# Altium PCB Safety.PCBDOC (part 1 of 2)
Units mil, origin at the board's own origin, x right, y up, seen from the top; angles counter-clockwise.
Board outline 11000 x 4400 mil, 6 copper layers (Top Layer, Multi Plane 1, Signal Layer1, Signal Layer2, Multi Plane 2, Bottom Layer); 613 components, 553 nets, 1937 pads, 0 vias.
Unrouted connection lines stored in the file: 1304.
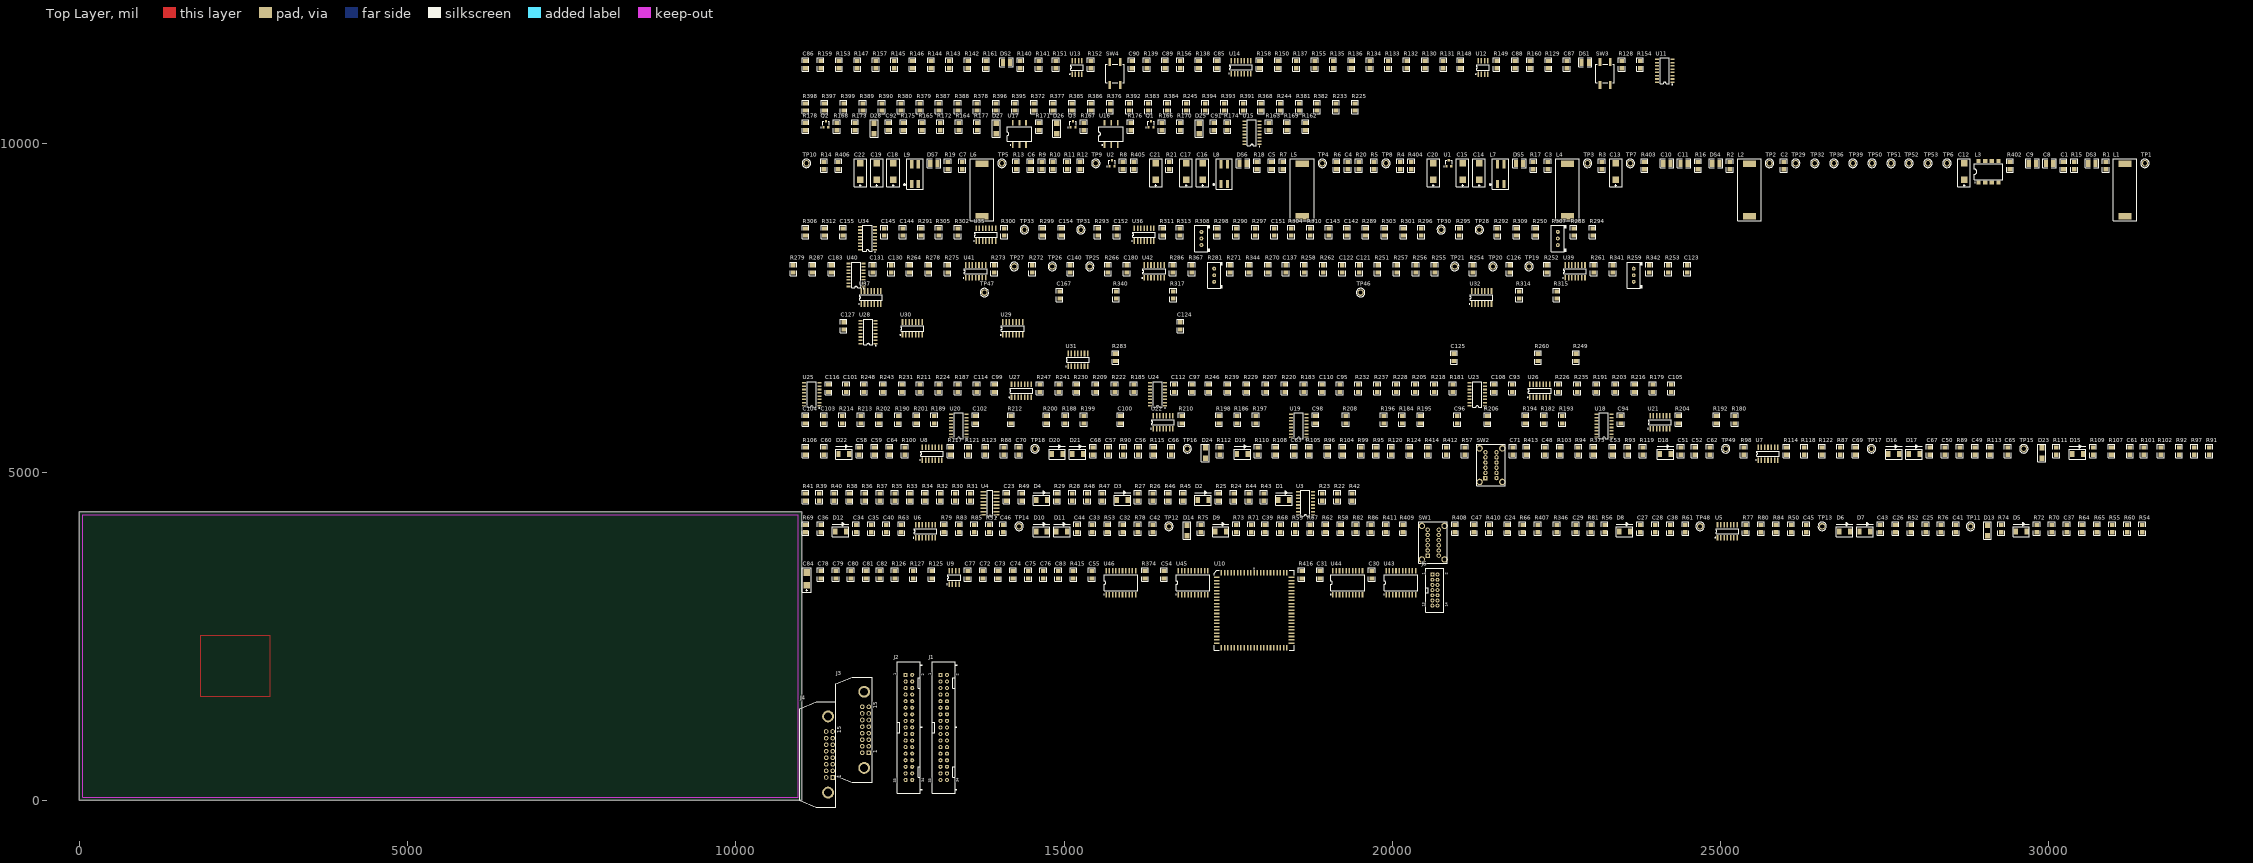
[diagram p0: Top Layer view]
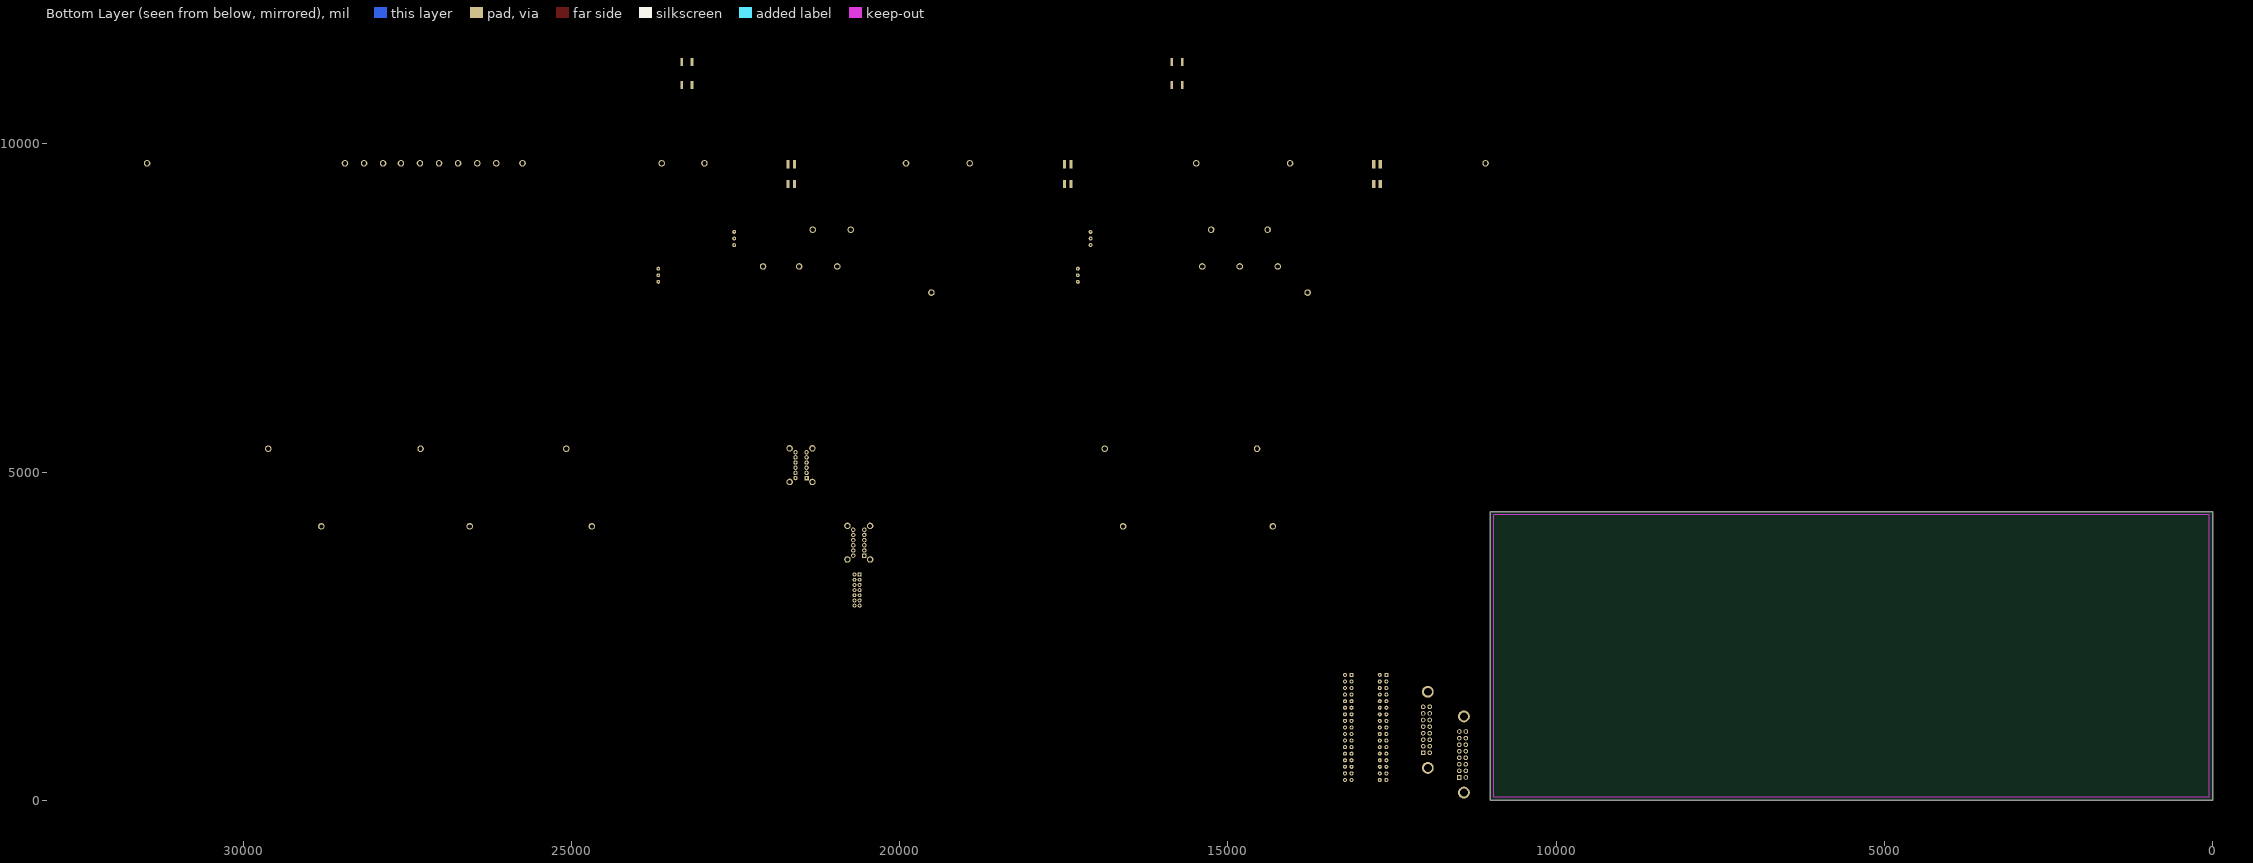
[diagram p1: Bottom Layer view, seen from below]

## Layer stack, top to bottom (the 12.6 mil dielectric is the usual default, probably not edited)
Top Layer: signal copper 1.4
Dielectric: core 12.6, FR-4, Dk 4.8
Multi Plane 1: signal copper 1.4
Dielectric: prepreg 12.6, FR-4, Dk 4.8
Signal Layer1: signal copper 1.4
Dielectric: core 12.6, FR-4, Dk 4.8
Signal Layer2: signal copper 1.4
Dielectric: prepreg 12.6, FR-4, Dk 4.8
Multi Plane 2: signal copper 1.4
Dielectric: core 12.6, FR-4, Dk 4.8
Bottom Layer: signal copper 1.4

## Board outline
0,0 11000,0 11000,4400 0,4400

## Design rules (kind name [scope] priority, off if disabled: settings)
RoomDefinition Sheet_Symbol_Overspeed [InComponentClass('Sheet_Symbol_Overspeed')] p1: confinementstyle=ConfineIn formatcopy=TRUE outline -1500,-2150 500,-2150 500,-1150 -1500,-1150
RoomDefinition Sheet_Symbol_Overcurrent_3 [InComponentClass('Sheet_Symbol_Overcurrent')] p2: confinementstyle=ConfineIn formatcopy=TRUE outline -1500,-2150 500,-2150 500,-1150 -1500,-1150
RoomDefinition Sheet_Symbol_Overcurrent_2 [InComponentClass('Sheet_Symbol_Overcurrent')] p3: confinementstyle=ConfineIn formatcopy=TRUE outline -1500,-2150 500,-2150 500,-1150 -1500,-1150
RoomDefinition Sheet_Symbol_Overcurrent_1 [InComponentClass('Sheet_Symbol_Overcurrent')] p4: confinementstyle=ConfineIn formatcopy=TRUE outline -1500,-2150 500,-2150 500,-1150 -1500,-1150
RoomDefinition Sheet_Symbol_Overcurrent [InComponentClass('Sheet_Symbol_Overcurrent')] p5: confinementstyle=ConfineIn formatcopy=TRUE outline -1500,-2150 500,-2150 500,-1150 -1500,-1150
RoomDefinition Sheet_Symbol_Input_Buffer_1 [InComponentClass('Sheet_Symbol_Input_Buffer')] p6: confinementstyle=ConfineIn formatcopy=TRUE outline -1500,-2150 500,-2150 500,-1150 -1500,-1150
RoomDefinition SB_PG1 [InComponentClass('SB_PG1')] p7: confinementstyle=ConfineIn formatcopy=TRUE outline -1500,-2150 500,-2150 500,-1150 -1500,-1150
RoomDefinition Sheet_Symbol_CPLD [InComponentClass('Sheet_Symbol_CPLD')] p8: confinementstyle=ConfineIn formatcopy=TRUE outline 11000,2273 20860,2273 20860,3650 11000,3650
RoomDefinition Sheet_Symbol_Dec_Tach [InComponentClass('Sheet_Symbol_Dec_Tach')] p9: confinementstyle=ConfineIn formatcopy=TRUE outline 11000,3601 31552,3601 31552,4351 11000,4351
RoomDefinition Sheet_Symbol_Encoder [InComponentClass('Sheet_Symbol_Encoder')] p10: confinementstyle=ConfineIn formatcopy=TRUE outline 11000,4301 19520,4301 19520,4831 11000,4831
RoomDefinition Sheet_Symbol_HA_Tach [InComponentClass('Sheet_Symbol_HA_Tach')] p11: confinementstyle=ConfineIn formatcopy=TRUE outline 11000,4782 32552,4782 32552,5532 11000,5532
RoomDefinition Sheet_Symbol_Input_Buffer [InComponentClass('Sheet_Symbol_Input_Buffer')] p12: confinementstyle=ConfineIn formatcopy=TRUE outline 11000,5961 24416,5961 24416,6490 11000,6490
RoomDefinition Sheet_Symbol_Power_Filter [InComponentClass('Sheet_Symbol_Power_Filter')] p13: confinementstyle=ConfineIn formatcopy=TRUE outline 11000,8820 31557,8820 31557,9880 11000,9880
RoomDefinition Sheet_Symbol_Relays [InComponentClass('Sheet_Symbol_Relays')] p14: confinementstyle=ConfineIn formatcopy=TRUE outline 11000,9930 18855,9930 18855,10474 11000,10474
RoomDefinition Sheet_Symbol_Spares [InComponentClass('Sheet_Symbol_Spares')] p15: confinementstyle=ConfineIn formatcopy=TRUE outline 11000,10450 19619,10450 19619,10774 11000,10774
RoomDefinition Sheet_Symbol_WD [InComponentClass('Sheet_Symbol_WD')] p16: confinementstyle=ConfineIn formatcopy=TRUE outline 11000,10823 24302,10823 24302,11419 11000,11419

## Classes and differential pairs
component class SB_PG1: J1 J2 J3 J4 J5
component class Sheet_Symbol_CPLD: C30 C31 C54 C55 C72 C73 C74 C75 C76 C77 C78 C79 C80 C81 C82 C83 C84 J6 R125 R126 R127 R374 R415 R416 U9 U10 U43 U44 U45 U46
component class Sheet_Symbol_Dec_Tach: C24 C25 C26 C27 C28 C29 C32 C33 C34 C35 C36 C37 C38 C39 C40 C41 C42 C43 C44 C45 C46 C47 D5 D6 D7 D8 D9 D10 D11 D12 D13 D14 R50 R51 R52 R53 R54 R55 R56 R58 R59 R60 R61 R62 R63 R64 R65 R66 R67 R68 R69 R70 R71 R72 R73 R74 R75 R76 R77 R78 R79 R80 R81 R82 R83 R84 R85 R86 R346 R407 R408 R409 R410 R411 SW1 TP11 TP12 TP13 TP14 TP48 U5 U6
component class Sheet_Symbol_Encoder: C23 D1 D2 D3 D4 R22 R23 R24 R25 R26 R27 R28 R29 R30 R31 R32 R33 R34 R35 R36 R37 R38 R39 R40 R41 R42 R43 R44 R45 R46 R47 R48 R49 U3 U4
component class Sheet_Symbol_HA_Tach: C48 C49 C50 C51 C52 C53 C56 C57 C58 C59 C60 C61 C62 C63 C64 C65 C66 C67 C68 C69 C70 C71 D15 D16 D17 D18 D19 D20 D21 D22 D23 D24 R57 R87 R88 R89 R90 R91 R92 R93 R94 R95 R96 R97 R98 R99 R100 R101 R102 R103 R104 R105 R106 R107 R108 R109 R110 R111 R112 R113 R114 R115 R117 R118 R119 R120 R121 R122 R123 R124 R373 R412 R413 R414 SW2 TP15 TP16 TP17 TP18 TP49 U7 U8
component class Sheet_Symbol_Input_Buffer: C93 C95 C97 C99 C101 C105 C108 C110 C112 C114 C116 R179 R181 R183 R185 R187 R191 R203 R205 R207 R209 R211 R216 R218 R220 R222 R224 R226 R228 R229 R230 R231 R232 R235 R237 R239 R241 R243 R246 R247 R248 U23 U24 U25 U26 U27
component class Sheet_Symbol_Overcurrent: C121 C122 C123 C126 C130 C131 C137 C140 C180 C183 R251 R252 R253 R254 R255 R256 R257 R258 R259 R261 R262 R264 R266 R270 R271 R272 R273 R275 R278 R279 R281 R286 R287 R341 R342 R344 R367 R369 TP19 TP20 TP21 TP25 TP26 TP27 U39 U40 U41 U42
component class Sheet_Symbol_Overspeed: C142 C143 C144 C145 C151 C152 C154 C155 R250 R288 R289 R290 R291 R292 R293 R294 R295 R296 R297 R298 R299 R300 R301 R302 R303 R304 R305 R306 R307 R308 R309 R310 R311 R312 R313 R370 TP28 TP30 TP31 TP33 U34 U35 U36
component class Sheet_Symbol_Power_Filter: C1 C2 C3 C4 C5 C6 C7 C8 C9 C10 C11 C12 C13 C14 C15 C16 C17 C18 C19 C20 C21 C22 DS3 DS4 DS5 DS6 DS7 L1 L2 L3 L4 L5 L6 L7 L8 L9 R1 R2 R3 R4 R5 R6 R7 R8 R9 R10 R11 R12 R13 R14 R15 R16 R17 R18 R19 R20 R21 R402 R403 R404 R405 R406 TP1 TP2 TP3 TP4 TP5 TP6 TP7 TP8 TP9 TP10 TP29 TP32 TP36 TP39 TP50 TP51 TP52 TP53 U1 U2
component class Sheet_Symbol_Relays: C91 C92 D25 D26 D27 D28 Q1 Q2 Q3 R162 R163 R164 R165 R166 R167 R168 R169 R170 R171 R172 R173 R174 R175 R176 R177 R178 U15 U16 U17
component class Sheet_Symbol_Spares: R225 R233 R244 R245 R368 R372 R376 R377 R378 R379 R380 R381 R382 R383 R384 R385 R386 R387 R388 R389 R390 R391 R392 R393 R394 R395 R396 R397 R398 R399
component class Sheet_Symbol_WD: C85 C86 C87 C88 C89 C90 DS1 DS2 R128 R129 R130 R131 R132 R133 R134 R135 R136 R137 R138 R139 R140 R141 R142 R143 R144 R145 R146 R147 R148 R149 R150 R151 R152 R153 R154 R155 R156 R157 R158 R159 R160 R161 SW3 SW4 U11 U12 U13 U14

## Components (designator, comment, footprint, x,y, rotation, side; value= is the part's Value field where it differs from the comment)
C1 "1uF" 1206 30222,9668 r90 top
C2 "1uF" 1206 25959,9668 r90 top
C3 "1uF" 1206 22367,9668 r90 top
C4 "1uF" 1206 19318,9668 r90 top
C5 "1uF" 1206 18157,9668 r90 top
C6 "1uF" 1206 14488,9668 r90 top
C7 "1uF" 1206 13447,9668 r90 top
C8 "22uF_15V" 1210 30010,9702 r0 top
C9 "22uF_15V" 1210 29747,9702 r0 top
C10 "22uF_15V" 1210 24180,9702 r0 top
C11 "22uF_15V" 1210 24443,9702 r0 top
C12 "100uF_25V" CAP_EIA_7343 28707,9578 r90 top
C13 "100uF_25V" CAP_EIA_7343 23403,9578 r90 top
C14 "100uF_25V" CAP_EIA_7343 21319,9578 r90 top
C15 "100uF_25V" CAP_EIA_7343 21068,9578 r90 top
C16 "100uF_25V" CAP_EIA_7343 17108,9578 r90 top
C17 "100uF_25V" CAP_EIA_7343 16857,9578 r90 top
C18 "100uF_25V" CAP_EIA_7343 12398,9578 r90 top
C19 "100uF_25V" CAP_EIA_7343 12147,9578 r90 top
C20 "470uF_10V" CAP_EIA_7343 20623,9578 r90 top
C21 "470uF_10V" CAP_EIA_7343 16397,9578 r90 top
C22 "470uF_10V" CAP_EIA_7343 11896,9578 r90 top
C23 "0.1uF" 1206 14122,4619 r90 top
C24 "1uF" 1206 21753,4139 r90 top
C25 "0.1uF" 1206 28122,4139 r90 top
C26 "0.1uF" 1206 27662,4139 r90 top
C27 "0.1uF" 1206 23772,4139 r90 top
C28 "0.1uF" 1206 24002,4139 r90 top
C29 "0.1uF" 1206 22792,4139 r90 top
C30 "0.1uF" 1206 19686,3438 r90 top
C31 "0.1uF" 1206 18896,3438 r90 top
C32 "0.1uF" 1206 15890,4139 r90 top
C33 "0.1uF" 1206 15430,4139 r90 top
C34 "0.1uF" 1206 11831,4139 r90 top
C35 "0.1uF" 1206 12061,4139 r90 top
C36 "0.1uF" 1206 11291,4139 r90 top
C37 "0.022uF" 1206 30272,4139 r90 top
C38 "0.022uF" 1206 24232,4139 r90 top
C39 "0.022uF" 1206 18060,4139 r90 top
C40 "0.022uF" 1206 12291,4139 r90 top
C41 "2200pF" 1206 28582,4139 r90 top
C42 "2200pF" 1206 16350,4139 r90 top
C43 "0.068uF" 1206 27432,4139 r90 top
C44 "0.068uF" 1206 15201,4139 r90 top
C45 "0.33uF" 1206 26302,4139 r90 top
C46 "0.33uF" 1206 14070,4139 r90 top
C47 "0.22uF" 1206 21243,4139 r90 top
C48 "1uF" 1206 22322,5320 r90 top
C49 "0.1uF" 1206 28872,5320 r90 top
C50 "0.1uF" 1206 28412,5320 r90 top
C51 "0.1uF" 1206 24392,5320 r90 top
C52 "0.1uF" 1206 24602,5320 r90 top
C53 "0.1uF" 1206 23352,5320 r90 top
C54 "0.1uF" 1206 16521,3438 r90 top
C55 "0.1uF" 1206 15421,3438 r90 top
C56 "0.1uF" 1206 16130,5320 r90 top
C57 "0.1uF" 1206 15670,5320 r90 top
C58 "0.1uF" 1206 11881,5320 r90 top
C59 "0.1uF" 1206 12111,5320 r90 top
C60 "0.1uF" 1206 11341,5320 r90 top
C61 "0.022uF" 1206 31232,5320 r90 top
C62 "0.022uF" 1206 24832,5320 r90 top
C63 "0.022uF" 1206 18500,5320 r90 top
C64 "0.022uF" 1206 12341,5320 r90 top
C65 "2200pF" 1206 29372,5320 r90 top
C66 "2200pF" 1206 16630,5320 r90 top
C67 "0.068uF" 1206 28182,5320 r90 top
C68 "0.068uF" 1206 15440,5320 r90 top
C69 "0.33uF" 1206 27052,5320 r90 top
C70 "0.33uF" 1206 14310,5320 r90 top
C71 "0.22uF" 1206 21833,5320 r90 top
C72 "1uF" 1206 13762,3438 r90 top
C73 "1uF" 1206 13992,3438 r90 top
C74 "1uF" 1206 14222,3438 r90 top
C75 "1uF" 1206 14452,3438 r90 top
C76 "1uF" 1206 14682,3438 r90 top
C77 "0.1uF" 1206 13532,3438 r90 top
C78 "0.1uF" 1206 11291,3438 r90 top
C79 "0.1uF" 1206 11521,3438 r90 top
C80 "0.1uF" 1206 11751,3438 r90 top
C81 "0.1uF" 1206 11981,3438 r90 top
C82 "0.1uF" 1206 12191,3438 r90 top
C83 "0.01uF" 1206 14911,3438 r90 top
C84 "10uF_25V" CAP_EIA_6032 11079,3375 r90 top
C85 "1uF" 1206 17327,11207 r90 top
C86 "1uF" 1206 11061,11207 r90 top
C87 "0.1uF" 1206 22656,11207 r90 top
C88 "0.1uF" 1206 21866,11207 r90 top
C89 "0.1uF" 1206 16537,11207 r90 top
C90 "0.1uF" 1206 16027,11207 r90 top
C91 "1uF" 1206 17276,10262 r90 top
C92 "1uF" 1206 12325,10262 r90 top
C93 "1uF" 1206 21826,6278 r90 top
C94 "1uF" 1206 23476,5799 r90 top
C95 "1uF" 1206 19198,6278 r90 top
C96 "1uF" 1206 20987,5799 r90 top
C97 "1uF" 1206 16948,6278 r90 top
C98 "1uF" 1206 18828,5799 r90 top
C99 "1uF" 1206 13940,6278 r90 top
C100 "1uF" 1206 15859,5799 r90 top
C101 "1uF" 1206 11680,6278 r90 top
C102 "1uF" 1206 13650,5799 r90 top
C103 "1uF" 1206 11341,5799 r90 top
C104 "1uF" 1206 11061,5799 r90 top
C105 "0.1uF" 1206 24246,6278 r90 top
C108 "1uF" 1206 21547,6278 r90 top
C110 "1uF" 1206 18928,6278 r90 top
C112 "1uF" 1206 16678,6278 r90 top
C114 "1uF" 1206 13670,6278 r90 top
C116 "1uF" 1206 11410,6278 r90 top
C121 "1uF" 1206 19494,8097 r90 top
C122 "1uF" 1206 19234,8097 r90 top
C123 "0.1uF" 1206 24490,8097 r90 top
C124 "0.1uF" 1206 16770,7228 r90 top
C125 "0.1uF" 1206 20937,6749 r90 top
C126 "0.1uF" 1206 21785,8097 r90 top
C127 "0.1uF" 1206 11641,7228 r90 top
C130 "1uF" 1206 12365,8097 r90 top
C131 "1uF" 1206 12085,8097 r90 top
C137 "0.1uF" 1206 18375,8097 r90 top
C140 "0.1uF" 1206 15095,8097 r90 top
C142 "1uF" 1206 19309,8657 r90 top
C143 "1uF" 1206 19029,8657 r90 top
C144 "1uF" 1206 12540,8657 r90 top
C145 "1uF" 1206 12260,8657 r90 top
C151 "0.1uF" 1206 18199,8657 r90 top
C152 "0.1uF" 1206 15800,8657 r90 top
C154 "0.1uF" 1206 14960,8657 r90 top
C155 "0.1uF" 1206 11631,8657 r90 top
C167 "0.1uF" 1206 14931,7699 r90 top
C180 "0.1uF" 1206 15955,8097 r90 top
C183 "0.1uF" 1206 11456,8097 r90 top
D1 "RS1DB-13" "DO-214AA (SMB) & MARKING" 18346,4575 r0 top
D2 "RS1DB-13" "DO-214AA (SMB) & MARKING" 17116,4575 r0 top
D3 "RS1DB-13" "DO-214AA (SMB) & MARKING" 15886,4575 r0 top
D4 "RS1DB-13" "DO-214AA (SMB) & MARKING" 14656,4575 r0 top
D5 "RS1DB-13" "DO-214AA (SMB) & MARKING" 29577,4095 r0 top
D6 "RS1DB-13" "DO-214AA (SMB) & MARKING" 26887,4095 r0 top
D7 "RS1DB-13" "DO-214AA (SMB) & MARKING" 27197,4095 r0 top
D8 "RS1DB-13" "DO-214AA (SMB) & MARKING" 23537,4095 r0 top
D9 "RS1DB-13" "DO-214AA (SMB) & MARKING" 17385,4095 r0 top
D10 "RS1DB-13" "DO-214AA (SMB) & MARKING" 14655,4095 r0 top
D11 "RS1DB-13" "DO-214AA (SMB) & MARKING" 14965,4095 r0 top
D12 "RS1DB-13" "DO-214AA (SMB) & MARKING" 11595,4095 r0 top
D13 "1SMA10CAT3G" "DO-214AC (SMA)" 29063,4111 r90 top
D14 "1SMA10CAT3G" "DO-214AC (SMA)" 16871,4111 r90 top
D15 "RS1DB-13" "DO-214AA (SMB) & MARKING" 30437,5276 r0 top
D16 "RS1DB-13" "DO-214AA (SMB) & MARKING" 27637,5276 r0 top
D17 "RS1DB-13" "DO-214AA (SMB) & MARKING" 27947,5276 r0 top
D18 "RS1DB-13" "DO-214AA (SMB) & MARKING" 24157,5276 r0 top
D19 "RS1DB-13" "DO-214AA (SMB) & MARKING" 17715,5276 r0 top
D20 "RS1DB-13" "DO-214AA (SMB) & MARKING" 14895,5276 r0 top
D21 "RS1DB-13" "DO-214AA (SMB) & MARKING" 15205,5276 r0 top
D22 "RS1DB-13" "DO-214AA (SMB) & MARKING" 11645,5276 r0 top
D23 "1SMA10CAT3G" "DO-214AC (SMA)" 29892,5292 r90 top
D24 "1SMA10CAT3G" "DO-214AC (SMA)" 17151,5292 r90 top
D25 "SMAJ26CA" "DO-214AC (SMA)" 17056,10234 r90 top
D26 "SMAJ26CA" "DO-214AC (SMA)" 14886,10234 r90 top
D27 "SMAJ26CA" "DO-214AC (SMA)" 13964,10234 r90 top
D28 "SMAJ26CA" "DO-214AC (SMA)" 12105,10234 r90 top
DS1 "LTST-C930KGKT" 1210 22937,11241 r0 top
DS2 "LTST-C930KGKT" 1210 14121,11241 r0 top
DS3 "LTST-C930KGKT" 1210 30654,9702 r0 top
DS4 "LTST-C930KGKT" 1210 24926,9702 r0 top
DS5 "LTST-C930KGKT" 1210 21935,9702 r0 top
DS6 "LTST-C930KGKT" 1210 17725,9702 r0 top
DS7 "LTST-C930KGKT" 1210 13015,9702 r0 top
J1 "Header_50_(25X2)_STR_SHD_LATCH_col1" HEADER_17x2_SHROUDED 13116,1912 r0 top
J2 "Header_50_(25X2)_STR_SHD_LATCH_col1" HEADER_17x2_SHROUDED 12586,1912 r0 top
J3 "Header_14_(7X2)_STR_SHD_LATCH_col1" 5499141-3 12025,825 r90 top
J4 "Header_16_(8X2)_STR_SHD_LATCH_col1" 5499141-3 11475,450 r90 top
J6 "Header_14_(7X2)_STR_SHD_col2" HDR_87831-1420 20608,3440 r0 top
L1 "8532-46LTR" 8532_inductor 31156,9300 r90 top
L2 "8532-46LTR" 8532_inductor 25438,9300 r90 top
L3 "ZJYS51R5-M4PAT-01" ZJYS51R5-M4PA_INDCUTOR 29079,9576 r0 top
L4 "8532-38LTR" 8532_inductor 22667,9300 r90 top
L5 "8532-38LTR" 8532_inductor 18627,9300 r90 top
L6 "8532-38LTR" 8532_inductor 13747,9300 r90 top
L7 "50105C" 5000_inductor 21649,9540 r90 top
L8 "50105C" 5000_inductor 17439,9540 r90 top
L9 "50105C" 5000_inductor 12728,9540 r90 top
Q1 "MMBT3906" SOT23 16322,10298 r0 top
Q2 "MMBT3906" SOT23 11371,10298 r0 top
Q3 "MMBT3904" SOT23 15136,10298 r0 top
R1 "0_jumper" 1206 30865,9668 r90 top
R2 "0_jumper" 1206 25138,9668 r90 top
R3 "0_jumper" 1206 23188,9668 r90 top
R4 "0_jumper" 1206 20118,9668 r90 top
R5 "0_jumper" 1206 19718,9668 r90 top
R6 "0_jumper" 1206 19148,9668 r90 top
R7 "0_jumper" 1206 18327,9668 r90 top
R8 "0_jumper" 1206 15892,9668 r90 top
R9 "0_jumper" 1206 14658,9668 r90 top
R10 "0_jumper" 1206 14828,9668 r90 top
R11 "0_jumper" 1206 15047,9668 r90 top
R12 "0_jumper" 1206 15247,9668 r90 top
R13 "0_jumper" 1206 14268,9668 r90 top
R14 "0_jumper" 1206 11341,9668 r90 top
R15 "15.8" 1206 30383,9668 r90 top
R16 "15.8" 1206 24655,9668 r90 top
R17 "3.01" 1206 22147,9668 r90 top
R18 "3.01" 1206 17937,9668 r90 top
R19 "3.01" 1206 13227,9668 r90 top
R20 "4870" 1206 19488,9668 r90 top
R21 "4870" 1206 16602,9668 r90 top
R22 "0_jumper" 1206 19160,4619 r90 top
R23 "0_jumper" 1206 18930,4619 r90 top
R24 "0_jumper" 1206 17581,4619 r90 top
R25 "0_jumper" 1206 17351,4619 r90 top
R26 "0_jumper" 1206 16351,4619 r90 top
R27 "0_jumper" 1206 16122,4619 r90 top
R28 "0_jumper" 1206 15122,4619 r90 top
R29 "0_jumper" 1206 14892,4619 r90 top
R30 "0_jumper" 1206 13340,4619 r90 top
R31 "0_jumper" 1206 13570,4619 r90 top
R32 "0_jumper" 1206 13111,4619 r90 top
R33 "0_jumper" 1206 12651,4619 r90 top
R34 "0_jumper" 1206 12881,4619 r90 top
R35 "0_jumper" 1206 12421,4619 r90 top
R36 "0_jumper" 1206 11961,4619 r90 top
R37 "0_jumper" 1206 12191,4619 r90 top
R38 "0_jumper" 1206 11731,4619 r90 top
R39 "0_jumper" 1206 11271,4619 r90 top
R40 "0_jumper" 1206 11501,4619 r90 top
R41 "0_jumper" 1206 11061,4619 r90 top
R42 "205" 1206 19390,4619 r90 top
R43 "205" 1206 18041,4619 r90 top
R44 "205" 1206 17811,4619 r90 top
R45 "205" 1206 16811,4619 r90 top
R46 "205" 1206 16581,4619 r90 top
R47 "205" 1206 15582,4619 r90 top
R48 "205" 1206 15352,4619 r90 top
R49 "205" 1206 14352,4619 r90 top
R50 "0_jumper" 1206 26072,4139 r90 top
R51 "0_jumper" 1206 13860,4139 r90 top
R52 "4870" 1206 27892,4139 r90 top
R53 "4870" 1206 15660,4139 r90 top
R54 "200000" 1206 31422,4139 r90 top
R55 "200000" 1206 30962,4139 r90 top
R56 "200000" 1206 23232,4139 r90 top
R57 "200000" 1206 21100,5320 r90 top
R58 "200000" 1206 19210,4139 r90 top
R59 "200000" 1206 18520,4139 r90 top
R60 "10000" 1206 31192,4139 r90 top
R61 "10000" 1206 24462,4139 r90 top
R62 "10000" 1206 18980,4139 r90 top
R63 "10000" 1206 12521,4139 r90 top
R64 "301000" 1206 30502,4139 r90 top
R65 "301000" 1206 30732,4139 r90 top
R66 "301000" 1206 21983,4139 r90 top
R67 "301000" 1206 18750,4139 r90 top
R68 "301000" 1206 18290,4139 r90 top
R69 "301000" 1206 11061,4139 r90 top
R70 "2000" 1206 30042,4139 r90 top
R71 "2000" 1206 17851,4139 r90 top
R72 "6810" 1206 29812,4139 r90 top
R73 "6810" 1206 17621,4139 r90 top
R74 "100" 1206 29272,4139 r90 top
R75 "100" 1206 17081,4139 r90 top
R76 "47500" 1206 28352,4139 r90 top
R77 "47500" 1206 25382,4139 r90 top
R78 "47500" 1206 16120,4139 r90 top
R79 "47500" 1206 13170,4139 r90 top
R80 "68100" 1206 25612,4139 r90 top
R81 "68100" 1206 23022,4139 r90 top
R82 "68100" 1206 19440,4139 r90 top
R83 "68100" 1206 13400,4139 r90 top
R84 "56200" 1206 25842,4139 r90 top
R85 "56200" 1206 13630,4139 r90 top
R86 "33200" 1206 19670,4139 r90 top
R87 "0_jumper" 1206 26822,5320 r90 top
R88 "0_jumper" 1206 14080,5320 r90 top
R89 "4870" 1206 28642,5320 r90 top
R90 "4870" 1206 15900,5320 r90 top
R91 "200000" 1206 32442,5320 r90 top
R92 "200000" 1206 31982,5320 r90 top
R93 "200000" 1206 23582,5320 r90 top
R94 "200000" 1206 22832,5320 r90 top
R95 "200000" 1206 19750,5320 r90 top
R96 "200000" 1206 19010,5320 r90 top
R97 "10000" 1206 32212,5320 r90 top
R98 "10000" 1206 25352,5320 r90 top
R99 "10000" 1206 19520,5320 r90 top
R100 "10000" 1206 12571,5320 r90 top
R101 "301000" 1206 31442,5320 r90 top
R102 "301000" 1206 31702,5320 r90 top
R103 "301000" 1206 22552,5320 r90 top
R104 "301000" 1206 19240,5320 r90 top
R105 "301000" 1206 18730,5320 r90 top
R106 "301000" 1206 11061,5320 r90 top
R107 "2000" 1206 30952,5320 r90 top
R108 "2000" 1206 18220,5320 r90 top
R109 "6810" 1206 30672,5320 r90 top
R110 "6810" 1206 17950,5320 r90 top
R111 "100" 1206 30112,5320 r90 top
R112 "100" 1206 17371,5320 r90 top
R113 "47500" 1206 29102,5320 r90 top
R114 "47500" 1206 26002,5320 r90 top
R115 "47500" 1206 16360,5320 r90 top
R117 "47500" 1206 13270,5320 r90 top
R118 "68100" 1206 26272,5320 r90 top
R119 "68100" 1206 23812,5320 r90 top
R120 "68100" 1206 19980,5320 r90 top
R121 "68100" 1206 13540,5320 r90 top
R122 "56200" 1206 26542,5320 r90 top
R123 "56200" 1206 13800,5320 r90 top
R124 "33200" 1206 20260,5320 r90 top
R125 "4750" 1206 12981,3438 r90 top
R126 "4750" 1206 12421,3438 r90 top
R127 "100000" 1206 12701,3438 r90 top
R128 "0_jumper" 1206 23492,11207 r90 top
R129 "0_jumper" 1206 22376,11207 r90 top
R130 "0_jumper" 1206 20496,11207 r90 top
R131 "0_jumper" 1206 20776,11207 r90 top
R132 "0_jumper" 1206 20216,11207 r90 top
R133 "0_jumper" 1206 19936,11207 r90 top
R134 "0_jumper" 1206 19656,11207 r90 top
R135 "0_jumper" 1206 19096,11207 r90 top
R136 "0_jumper" 1206 19376,11207 r90 top
R137 "0_jumper" 1206 18536,11207 r90 top
R138 "0_jumper" 1206 17047,11207 r90 top
R139 "0_jumper" 1206 16257,11207 r90 top
R140 "0_jumper" 1206 14333,11207 r90 top
R141 "0_jumper" 1206 14613,11207 r90 top
R142 "0_jumper" 1206 13530,11207 r90 top
R143 "0_jumper" 1206 13250,11207 r90 top
R144 "0_jumper" 1206 12971,11207 r90 top
R145 "0_jumper" 1206 12411,11207 r90 top
R146 "0_jumper" 1206 12691,11207 r90 top
R147 "0_jumper" 1206 11851,11207 r90 top
R148 "10000" 1206 21036,11207 r90 top
R149 "10000" 1206 21587,11207 r90 top
R150 "10000" 1206 18256,11207 r90 top
R151 "10000" 1206 14873,11207 r90 top
R152 "10000" 1206 15404,11207 r90 top
R153 "10000" 1206 11571,11207 r90 top
R154 "2000" 1206 23772,11207 r90 top
R155 "2000" 1206 18816,11207 r90 top
R156 "2000" 1206 16767,11207 r90 top
R157 "2000" 1206 12131,11207 r90 top
R158 "100" 1206 17976,11207 r90 top
R159 "100" 1206 11291,11207 r90 top
R160 "249" 1206 22096,11207 r90 top
R161 "249" 1206 13810,11207 r90 top
R162 "0_jumper" 1206 18675,10262 r90 top
R163 "0_jumper" 1206 18115,10262 r90 top
R164 "0_jumper" 1206 13394,10262 r90 top
R165 "0_jumper" 1206 12834,10262 r90 top
R166 "4870" 1206 16486,10262 r90 top
R167 "4870" 1206 15300,10262 r90 top
R168 "4870" 1206 11535,10262 r90 top
R169 "10000" 1206 18395,10262 r90 top
R170 "10000" 1206 16766,10262 r90 top
R171 "10000" 1206 14616,10262 r90 top
R172 "10000" 1206 13114,10262 r90 top
R173 "10000" 1206 11815,10262 r90 top
R174 "100" 1206 17486,10262 r90 top
R175 "100" 1206 12554,10262 r90 top
R176 "249" 1206 16012,10262 r90 top
R177 "249" 1206 13674,10262 r90 top
R178 "249" 1206 11061,10262 r90 top
R179 "10000" 1206 23966,6278 r90 top
R180 "10000" 1206 25215,5799 r90 top
R181 "10000" 1206 20917,6278 r90 top
R182 "10000" 1206 22307,5799 r90 top
R183 "10000" 1206 18648,6278 r90 top
R184 "10000" 1206 20147,5799 r90 top
R185 "10000" 1206 16059,6278 r90 top
R186 "10000" 1206 17639,5799 r90 top
R187 "10000" 1206 13380,6278 r90 top
R188 "10000" 1206 15019,5799 r90 top
R189 "10000" 1206 13021,5799 r90 top
R190 "10000" 1206 12471,5799 r90 top
R191 "2000" 1206 23106,6278 r90 top
R192 "2000" 1206 24935,5799 r90 top
R193 "2000" 1206 22587,5799 r90 top
R194 "2000" 1206 22027,5799 r90 top
R195 "2000" 1206 20427,5799 r90 top
R196 "2000" 1206 19868,5799 r90 top
R197 "2000" 1206 17919,5799 r90 top
R198 "2000" 1206 17359,5799 r90 top
R199 "2000" 1206 15299,5799 r90 top
R200 "2000" 1206 14730,5799 r90 top
R201 "2000" 1206 12751,5799 r90 top
R202 "2000" 1206 12181,5799 r90 top
R203 "100" 1206 23396,6278 r90 top
R204 "100" 1206 24356,5799 r90 top
R205 "100" 1206 20347,6278 r90 top
R206 "100" 1206 21447,5799 r90 top
R207 "100" 1206 18068,6278 r90 top
R208 "100" 1206 19288,5799 r90 top
R209 "100" 1206 15479,6278 r90 top
R210 "100" 1206 16789,5799 r90 top
R211 "100" 1206 12800,6278 r90 top
R212 "100" 1206 14190,5799 r90 top
R213 "100" 1206 11901,5799 r90 top
R214 "100" 1206 11621,5799 r90 top
R216 "10000" 1206 23686,6278 r90 top
R218 "10000" 1206 20637,6278 r90 top
R220 "10000" 1206 18358,6278 r90 top
R222 "10000" 1206 15769,6278 r90 top
R224 "10000" 1206 13090,6278 r90 top
R225 "0_jumper" 1206 19429,10562 r90 top
R226 "1000" 1206 22526,6278 r90 top
R228 "2000" 1206 20057,6278 r90 top
R229 "2000" 1206 17778,6278 r90 top
R230 "2000" 1206 15189,6278 r90 top
R231 "2000" 1206 12530,6278 r90 top
R232 "1000" 1206 19478,6278 r90 top
R233 "0_jumper" 1206 19139,10562 r90 top
R235 "100" 1206 22816,6278 r90 top
R237 "100" 1206 19768,6278 r90 top
R239 "100" 1206 17488,6278 r90 top
R241 "100" 1206 14919,6278 r90 top
R243 "100" 1206 12240,6278 r90 top
R244 "0_jumper" 1206 18289,10562 r90 top
R245 "0_jumper" 1206 16860,10562 r90 top
R246 "1000" 1206 17198,6278 r90 top
R247 "1000" 1206 14629,6278 r90 top
R248 "1000" 1206 11950,6278 r90 top
R249 "10000" 1206 22796,6749 r90 top
R250 "20000" 1206 22179,8657 r90 top
R251 "0_jumper" 1206 19774,8097 r90 top
R252 "4870" 1206 22355,8097 r90 top
R253 "10000" 1206 24200,8097 r90 top
R254 "10000" 1206 21224,8097 r90 top
R255 "10000" 1206 20644,8097 r90 top
R256 "6810" 1206 20354,8097 r90 top
R257 "100000" 1206 20064,8097 r90 top
R258 "100000" 1206 18655,8097 r90 top
R259 "Top_Seal_10k" Pot_3296W 23675,7999 r90 top
R260 "40200" 1206 22216,6749 r90 top
R261 "1210" 1206 23065,8097 r90 top
R262 "1210" 1206 18945,8097 r90 top
R264 "0_jumper" 1206 12645,8097 r90 top
R266 "4870" 1206 15666,8097 r90 top
R270 "10000" 1206 18105,8097 r90 top
R271 "10000" 1206 17525,8097 r90 top
R272 "10000" 1206 14515,8097 r90 top
R273 "10000" 1206 13934,8097 r90 top
R275 "6810" 1206 13225,8097 r90 top
R278 "100000" 1206 12935,8097 r90 top
R279 "100000" 1206 10876,8097 r90 top
R281 "Top_Seal_10k" Pot_3296W 17285,7999 r90 top
R283 "40200" 1206 15781,6749 r90 top
R286 "1210" 1206 16655,8097 r90 top
R287 "1210" 1206 11166,8097 r90 top
R288 "0_jumper" 1206 22759,8657 r90 top
R289 "0_jumper" 1206 19589,8657 r90 top
R290 "0_jumper" 1206 17619,8657 r90 top
R291 "0_jumper" 1206 12820,8657 r90 top
R292 "4870" 1206 21599,8657 r90 top
R293 "4870" 1206 15510,8657 r90 top
R294 "10000" 1206 23049,8657 r90 top
R295 "10000" 1206 21019,8657 r90 top
R296 "10000" 1206 20439,8657 r90 top
R297 "10000" 1206 17909,8657 r90 top
R298 "10000" 1206 17329,8657 r90 top
R299 "10000" 1206 14670,8657 r90 top
R300 "10000" 1206 14089,8657 r90 top
R301 "6810" 1206 20169,8657 r90 top
R302 "6810" 1206 13380,8657 r90 top
R303 "100000" 1206 19879,8657 r90 top
R304 "100000" 1206 18459,8657 r90 top
R305 "100000" 1206 13090,8657 r90 top
R306 "100000" 1206 11061,8657 r90 top
R307 "Top_Seal_10k" Pot_3296W 22519,8559 r90 top
R308 "Top_Seal_10k" Pot_3296W 17090,8559 r90 top
R309 "1210" 1206 21889,8657 r90 top
R310 "1210" 1206 18749,8657 r90 top
R311 "1210" 1206 16500,8657 r90 top
R312 "1210" 1206 11351,8657 r90 top
R313 "20000" 1206 16760,8657 r90 top
R314 "15000" 1206 21931,7699 r90 top
R315 "0_jumper" 1206 22501,7699 r90 top
R317 "0_jumper" 1206 16661,7699 r90 top
R340 "15000" 1206 15791,7699 r90 top
R341 "15000" 1206 23355,8097 r90 top
R342 "0_jumper" 1206 23910,8097 r90 top
R344 "0_jumper" 1206 17815,8097 r90 top
R346 "4870" 1206 22503,4139 r90 top
R367 "15000" 1206 16945,8097 r90 top
R368 "10000" 1206 17999,10562 r90 top
R372 "10000" 1206 14540,10562 r90 top
R373 "4870" 1206 23062,5320 r90 top
R374 "10000" 1206 16231,3438 r90 top
R376 "0_jumper" 1206 15700,10562 r90 top
R377 "0_jumper" 1206 14830,10562 r90 top
R378 "0_jumper" 1206 13670,10562 r90 top
R379 "0_jumper" 1206 12801,10562 r90 top
R380 "0_jumper" 1206 12511,10562 r90 top
R381 "0_jumper" 1206 18579,10562 r90 top
R382 "0_jumper" 1206 18849,10562 r90 top
R383 "0_jumper" 1206 16280,10562 r90 top
R384 "0_jumper" 1206 16570,10562 r90 top
R385 "0_jumper" 1206 15120,10562 r90 top
R386 "0_jumper" 1206 15410,10562 r90 top
R387 "0_jumper" 1206 13091,10562 r90 top
R388 "0_jumper" 1206 13380,10562 r90 top
R389 "0_jumper" 1206 11931,10562 r90 top
R390 "0_jumper" 1206 12221,10562 r90 top
R391 "0_jumper" 1206 17729,10562 r90 top
R392 "0_jumper" 1206 15990,10562 r90 top
R393 "0_jumper" 1206 17439,10562 r90 top
R394 "0_jumper" 1206 17150,10562 r90 top
R395 "0_jumper" 1206 14250,10562 r90 top
R396 "0_jumper" 1206 13960,10562 r90 top
R397 "0_jumper" 1206 11351,10562 r90 top
R398 "0_jumper" 1206 11061,10562 r90 top
R399 "10000" 1206 11641,10562 r90 top
R402 "1210" 1206 29406,9668 r90 top
R403 "1210" 1206 23839,9668 r90 top
R404 "249" 1206 20288,9668 r90 top
R405 "249" 1206 16062,9668 r90 top
R406 "249" 1206 11561,9668 r90 top
R407 "200000" 1206 22213,4139 r90 top
R408 "200000" 1206 20953,4139 r90 top
R409 "100" 1206 20160,4139 r90 top
R410 "20000" 1206 21473,4139 r90 top
R411 "20000" 1206 19900,4139 r90 top
R412 "100" 1206 20820,5320 r90 top
R413 "20000" 1206 22043,5320 r90 top
R414 "20000" 1206 20540,5320 r90 top
R415 "0_jumper" 1206 15141,3438 r90 top
R416 "0_jumper" 1206 18617,3438 r90 top
SW1 "MSS420004" MSS420004 20621,3926 r90 top
SW2 "MSS420004" MSS420004 21501,5107 r90 top
SW3 "TL6120AF300QG" SWITCH_TL6120AF300QG 23240,11071 r0 top
SW4 "TL6120AF300QG" SWITCH_TL6120AF300QG 15775,11071 r0 top
TP1 "TP_5005" TP_COMPACT 31461,9704 r0 top
TP2 "TP_5005" TP_COMPACT 25743,9704 r0 top
TP3 "TP_5005" TP_COMPACT 22972,9704 r0 top
TP4 "TP_5005" TP_COMPACT 18932,9704 r0 top
TP5 "TP_5005" TP_COMPACT 14052,9704 r0 top
TP6 "TP_5006" TP_COMPACT 28447,9704 r0 top
TP7 "TP_5006" TP_COMPACT 23623,9704 r0 top
TP8 "TP_5006" TP_COMPACT 19902,9704 r0 top
TP9 "TP_5006" TP_COMPACT 15482,9704 r0 top
TP10 "TP_5006" TP_COMPACT 11075,9704 r0 top
TP11 "TP_5009" TP_COMPACT 28807,4175 r0 top
TP12 "TP_5009" TP_COMPACT 16595,4175 r0 top
TP13 "TP_5008" TP_COMPACT 26546,4175 r0 top
TP14 "TP_5008" TP_COMPACT 14315,4175 r0 top
TP15 "TP_5009" TP_COMPACT 29616,5356 r0 top
TP16 "TP_5009" TP_COMPACT 16875,5356 r0 top
TP17 "TP_5008" TP_COMPACT 27296,5356 r0 top
TP18 "TP_5008" TP_COMPACT 14555,5356 r0 top
TP19 "TP_5007" TP_COMPACT 22079,8133 r0 top
TP20 "TP_5007" TP_COMPACT 21529,8133 r0 top
TP21 "TP_5007" TP_COMPACT 20949,8133 r0 top
TP25 "TP_5007" TP_COMPACT 15390,8133 r0 top
TP26 "TP_5007" TP_COMPACT 14819,8133 r0 top
TP27 "TP_5007" TP_COMPACT 14239,8133 r0 top
TP28 "TP_5007" TP_COMPACT 21323,8693 r0 top
TP29 "TP_5006" TP_COMPACT 26143,9704 r0 top
TP30 "TP_5007" TP_COMPACT 20743,8693 r0 top
TP31 "TP_5007" TP_COMPACT 15254,8693 r0 top
TP32 "TP_5006" TP_COMPACT 26433,9704 r0 top
TP33 "TP_5007" TP_COMPACT 14394,8693 r0 top
TP36 "TP_5006" TP_COMPACT 26724,9704 r0 top
TP39 "TP_5006" TP_COMPACT 27014,9704 r0 top
TP46 "TP_5007" TP_COMPACT 19515,7735 r0 top
TP47 "TP_5007" TP_COMPACT 13785,7735 r0 top
TP48 "TP_5007" TP_COMPACT 24687,4175 r0 top
TP49 "TP_5007" TP_COMPACT 25076,5356 r0 top
TP50 "TP_5006" TP_COMPACT 27305,9704 r0 top
TP51 "TP_5006" TP_COMPACT 27595,9704 r0 top
TP52 "TP_5006" TP_COMPACT 27866,9704 r0 top
TP53 "TP_5006" TP_COMPACT 28156,9704 r0 top
U1 "LM4040DIM3-5.0/NOPB" SOT23 20859,9704 r0 top
U2 "LM4040DIM3-5.0/NOPB" SOT23 15728,9704 r0 top
U3 "TLP281-4" SOIC_16_C5.85 18675,4525 r90 top
U4 "DS26LS32ACM" SOIC_16_NARROW 13871,4525 r90 top
U5 "OPA4277UA" SOIC_14_Narrow 25101,4100 r0 top
U6 "OPA4277UA" SOIC_14_Narrow 12889,4100 r0 top
U7 "OPA4277UA" SOIC_14_Narrow 25720,5281 r0 top
U8 "OPA4277UA" SOIC_14_Narrow 12989,5281 r0 top
U9 "TS555IDT" SOIC_8_NARROW 13324,3395 r0 top
U10 "XC9572-15PC84C" PLCC_84 17893,2897 r0 top
U11 "TLP281-4" SOIC_16_C5.85 24147,11113 r90 top
U12 "MAX1232ESA+" SOIC_8_NARROW 21379,11164 r0 top
U13 "MAX1232ESA+" SOIC_8_NARROW 15196,11164 r0 top
U14 "M74HC14RM13TR" SOIC_14_Narrow 17695,11168 r0 top
U15 "TLP281-4" SOIC_16_C5.85 17860,10168 r90 top
U16 "PS710EL-1A-A" SO_6_254P 15765,10152 r0 top
U17 "PS710EL-1A-A" SO_6_254P 14369,10152 r0 top
U18 "TLP281-4" SOIC_16_C5.85 23221,5705 r90 top
U19 "TLP281-4" SOIC_16_C5.85 18573,5705 r90 top
U20 "TLP281-4" SOIC_16_C5.85 13395,5705 r90 top
U21 "M74HC14RM13TR" SOIC_14_Narrow 24074,5760 r0 top
U22 "M74HC14RM13TR" SOIC_14_Narrow 16507,5760 r0 top
U23 "TLP281-4" SOIC_16_C5.85 21291,6184 r90 top
U24 "TLP281-4" SOIC_16_C5.85 16423,6184 r90 top
U25 "TLP281-4" SOIC_16_C5.85 11155,6184 r90 top
U26 "M74HC14RM13TR" SOIC_14_Narrow 22244,6239 r0 top
U27 "M74HC14RM13TR" SOIC_14_Narrow 14348,6239 r0 top
U28 "TLP281-4" SOIC_16_C5.85 12015,7134 r90 top
U29 "OPA4277UA" SOIC_14_Narrow 14217,7189 r0 top
U30 "M74HC14RM13TR" SOIC_14_Narrow 12688,7189 r0 top
U31 "LM339DR2G" SOIC_14_Narrow 15210,6710 r0 top
U32 "LM339DR2G" SOIC_14_Narrow 21359,7660 r0 top
U34 "TLP281-4" SOIC_16_C5.85 12005,8563 r90 top
U35 "OPA4277UA" SOIC_14_Narrow 13808,8618 r0 top
U36 "LM339DR2G" SOIC_14_Narrow 16218,8618 r0 top
U37 "M74HC14RM13TR" SOIC_14_Narrow 12059,7660 r0 top
U39 "LM339DR2G" SOIC_14_Narrow 22783,8058 r0 top
U40 "TLP281-4" SOIC_16_C5.85 11830,8003 r90 top
U41 "OPA4277UA" SOIC_14_Narrow 13653,8058 r0 top
U42 "LM339DR2G" SOIC_14_Narrow 16373,8058 r0 top
U43 "M74HCT541M1R" SOIC_20_WIDE 20129,3316 r0 top
U44 "M74HCT541M1R" SOIC_20_WIDE 19319,3316 r0 top
U45 "M74HCT541M1R" SOIC_20_WIDE 16964,3316 r0 top
U46 "M74HCT541M1R" SOIC_20_WIDE 15864,3316 r0 top

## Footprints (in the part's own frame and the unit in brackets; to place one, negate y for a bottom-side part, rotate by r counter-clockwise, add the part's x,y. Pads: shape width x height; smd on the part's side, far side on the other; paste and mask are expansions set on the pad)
1206 [mm]
  rect 1.6x1.8 smd: 1(-1.4,0) 2(1.4,0)
  silkscreen extent -2.6,-1.3 2.6,1.3
1210 [mm]
  rect 1.6x2.7 smd: 1(-1.4,0) 2(1.4,0)
  silkscreen extent -2.6,-1.75 2.6,1.75
5000_inductor [mil] "Inductor, Common Mode"
  rect 125x50 all layers, no hole: 1(-150,50) 2(-150,-50) 3(150,-50) 4(150,50)
  silkscreen extent -230,-125 230,170
8532_inductor [mil] "Inductor, 8532 series"
  rect 100x200 smd: 1(-400,0) 2(400,0)
  silkscreen extent -470,-180 470,180
5499141-3 [mil] "Header, 16-Pin, Dual row, Right Angle, Latch"
  rect 70x70 hole 40: 1(-100,0)
  round 70 hole 40: 2(-100,100) 3(0,0) 4(0,100) 5(100,0) 6(100,100) 7(200,0) 8(200,100) 9(300,0) 10(300,100) 11(400,0) 12(400,100) 13(500,0) 14(500,100) 15(600,0) 16(600,100)
  round 180 hole 120: ""(-330,71) ""(830,71)
  silkscreen extent -550,-50 1050,500
CAP_EIA_6032 [mm]
  rect 2.6x2.5 smd: 1(-2.5,0) 2(2.5,0)
  silkscreen extent -5.2,-1.78 4.2,1.78
CAP_EIA_7343 [mm]
  rect 2.6x2.5 smd: 1(-3.2,0) 2(3.2,0)
  silkscreen extent -5.9,-2.45 4.9,2.45
"DO-214AA (SMB) & MARKING" [mm]
  rect 1.7x2.2 smd: A(-2.1,0) K(2.1,0)
  silkscreen extent -3.17,-2.03 3.17,3.68
"DO-214AC (SMA)" [mil] "SMA"
  rect 80x80 smd: A(-78.5,0) K(78.5,0)
  silkscreen extent -130,-60 130,60
HDR_87831-1420 [mil] "Header, 7x2, straight, shroud, common use for JTAG"
  rect 60x60 hole 28: 1(0,0)
  round 60 hole 28: 2(78.74,0) 3(0,-78.74) 5(0,-157.48) 6(78.74,-157.48) 7(0,-236.22) 8(78.74,-236.22) 9(0,-314.96) 10(78.74,-314.96) 11(0,-393.7) 12(78.74,-393.7) 13(0,-472.44) 14(78.74,-472.44)
  round 59.06 hole 28: 4(78.74,-78.74)
  silkscreen extent -98,-571 177,98
HEADER_17x2_SHROUDED [mil] "Header, 17x2, shrouded, thru hole, vertical"
  rect 62x62 hole 28: 1(0,0)
  round 62 hole 28: 2(100,0) 3(0,-100) 4(100,-100) 5(0,-200) 6(100,-200) 7(0,-300) 8(100,-300) 9(0,-400) 10(100,-400) 11(0,-500) 12(100,-500) 13(0,-600) 14(100,-600) 15(0,-700) 16(100,-700) 17(0,-800) 18(100,-800) 19(0,-900) 20(100,-900) 21(0,-1000) 22(100,-1000) 23(0,-1100) 24(100,-1100) 25(0,-1200) 26(100,-1200) 27(0,-1300) 28(100,-1300) 29(0,-1400) 30(100,-1400) 31(0,-1500) 32(100,-1500) 33(0,-1600) 34(100,-1600)
  silkscreen extent -125,-1800 255,200
MSS420004 [mm] "Switch, Slide, 4PDT"
  rect 1.7x1.7 hole 0.9: 1(-5,2.15)
  round 1.7 hole 0.9: 2(-3,2.15) 3(-1,2.15) 4(1,2.15) 5(3,2.15) 6(5,2.15) 7(-5,-2.15) 8(-3,-2.15) 9(-1,-2.15) 10(1,-2.15) 11(3,-2.15) 12(5,-2.15)
  round 2.5 hole 1.5: ""(-6.5,-4.4) ""(-6.5,4.4) ""(6.5,-4.4) ""(6.5,4.4)
  silkscreen extent -8,-5.5 8,5.5
PLCC_84 [mm] "PLCC, 84 pin"
  rect 0.6x2.2 smd: 1(0,14.5) 2(-1.27,14.5) 3(-2.54,14.5) 4(-3.81,14.5) 5(-5.08,14.5) 6(-6.35,14.5) 7(-7.62,14.5) 8(-8.89,14.5) 9(-10.16,14.5) 10(-11.43,14.5) 11(-12.7,14.5) 33(-12.7,-14.5) 34(-11.43,-14.5) 35(-10.16,-14.5) 36(-8.89,-14.5) 37(-7.62,-14.5) 38(-6.35,-14.5) 39(-5.08,-14.5) 40(-3.81,-14.5) 41(-2.54,-14.5) 42(-1.27,-14.5) 43(0,-14.5) 44(1.27,-14.5) 45(2.54,-14.5) 46(3.81,-14.5) 47(5.08,-14.5) 48(6.35,-14.5) 49(7.62,-14.5) 50(8.89,-14.5) 51(10.16,-14.5) 52(11.43,-14.5) 53(12.7,-14.5) 75(12.7,14.5) 76(11.43,14.5) 77(10.16,14.5) 78(8.89,14.5) 79(7.62,14.5) 80(6.35,14.5) 81(5.08,14.5) 82(3.81,14.5) 83(2.54,14.5) 84(1.27,14.5)
  rect 2.2x0.6 smd: 12(-14.5,12.7) 13(-14.5,11.43) 14(-14.5,10.16) 15(-14.5,8.89) 16(-14.5,7.62) 17(-14.5,6.35) 18(-14.5,5.08) 19(-14.5,3.81) 20(-14.5,2.54) 21(-14.5,1.27) 22(-14.5,0) 23(-14.5,-1.27) 24(-14.5,-2.54) 25(-14.5,-3.81) 26(-14.5,-5.08) 27(-14.5,-6.35) 28(-14.5,-7.62) 29(-14.5,-8.89) 30(-14.5,-10.16) 31(-14.5,-11.43) 32(-14.5,-12.7) 54(14.5,-12.7) 55(14.5,-11.43) 56(14.5,-10.16) 57(14.5,-8.89) 58(14.5,-7.62) 59(14.5,-6.35) 60(14.5,-5.08) 61(14.5,-3.81) 62(14.5,-2.54) 63(14.5,-1.27) 64(14.5,0) 65(14.5,1.27) 66(14.5,2.54) 67(14.5,3.81) 68(14.5,5.08) 69(14.5,6.35) 70(14.5,7.62) 71(14.5,8.89) 72(14.5,10.16) 73(14.5,11.43) 74(14.5,12.7)
  silkscreen extent -15.48,-15.49 15.48,16.32
Pot_3296W [mil] "Pot, Top Adjust"
  round 60 hole 25: 1(-100,0) 2(0,0) 3(100,0)
  silkscreen extent -205,-130 205,100
SO_6_254P [mm] "Surface mount, 6 pin, 2.54mm spacing"
  rect 0.65x2.2 smd: 1(-3.81,-4.3) 2(-1.27,-4.3) 3(1.27,-4.3) 4(1.27,4.3) 5(-1.27,4.3) 6(-3.81,4.3)
  silkscreen extent -6,-4.42 3.5,2.8
SOIC_8_NARROW [mm] "8 pin Narrow SOIC"
  rect 0.6x2.2 smd: 1(-1.905,-2.6) 2(-0.635,-2.6) 3(0.635,-2.6) 4(1.905,-2.6) 5(1.905,2.6) 6(0.635,2.6) 7(-0.635,2.6) 8(-1.905,2.6)
  silkscreen extent -2.88,-2.72 2.5,1.1
SOIC_14_Narrow [mm] "14 pin Narrow SOIC"
  rect 0.6x2.2 smd: 1(-3.81,-2.5) 2(-2.54,-2.5) 3(-1.27,-2.5) 4(0,-2.5) 5(1.27,-2.5) 6(2.54,-2.5) 7(3.81,-2.5) 8(3.81,2.5) 9(2.54,2.5) 10(1.27,2.5) 11(0,2.5) 12(-1.27,2.5) 13(-2.54,2.5) 14(-3.81,2.5)
  silkscreen extent -4.78,-2.62 4.38,1
SOIC_16_C5.85 [mm]
  rect 0.6x1.55 smd: 1(-4.445,-2.925) 2(-3.175,-2.925) 3(-1.905,-2.925) 4(-0.635,-2.925) 5(0.635,-2.925) 6(1.905,-2.925) 7(3.175,-2.925) 8(4.445,-2.925) 9(4.445,2.925) 10(3.175,2.925) 11(1.905,2.925) 12(0.635,2.925) 13(-0.635,2.925) 14(-1.905,2.925) 15(-3.175,2.925) 16(-4.445,2.925)
  silkscreen extent -5.39,-3.05 5,1.75
SOIC_16_NARROW [mm] "16 pin Narrow SOIC"
  rect 0.6x2.2 smd: 1(-4.445,-2.5) 2(-3.175,-2.5) 3(-1.905,-2.5) 4(-0.635,-2.5) 5(0.635,-2.5) 6(1.905,-2.5) 7(3.175,-2.5) 8(4.445,-2.5) 9(4.445,2.5) 10(3.175,2.5) 11(1.905,2.5) 12(0.635,2.5) 13(-0.635,2.5) 14(-1.905,2.5) 15(-3.175,2.5) 16(-4.445,2.5)
  silkscreen extent -5.42,-2.63 5,1
SOIC_20_WIDE [mm] "Small Outline; 20 Leads; Body Width 7.5 mm; Pitch 1.27 mm"
  rect 0.6x2.2 smd: 1(-5.715,-4.6) 2(-4.445,-4.6) 3(-3.175,-4.6) 4(-1.905,-4.6) 5(-0.635,-4.6) 6(0.635,-4.6) 7(1.905,-4.6) 8(3.175,-4.6) 9(4.445,-4.6) 10(5.715,-4.6) 11(5.715,4.6) 12(4.445,4.6) 13(3.175,4.6) 14(1.905,4.6) 15(0.635,4.6) 16(-0.635,4.6) 17(-1.905,4.6) 18(-3.175,4.6) 19(-4.445,4.6) 20(-5.715,4.6)
  silkscreen extent -6.69,-4.72 6.53,3.1
SOT23 [mm]
  rect 0.85x1 smd: 1(-0.95,-1.2) 2(0.95,-1.2) 3(0,1.2)
  silkscreen extent -2.05,-1.32 1.28,1.2
SWITCH_TL6120AF300QG [mm] "Switch, Tactile, SPST, NO"
  rect 1x3.1 all layers, no hole: 1(2,4.5) 2(-2,4.5) 3(2,-4.5) 4(-2,-4.5)
  silkscreen extent -3.6,-3.6 3.6,3.6
TP_COMPACT [mil] "5005-5009 Compact Test Points"
  round 100 hole 63: 1(0,0)
  silkscreen extent -65,-65 65,65
ZJYS51R5-M4PA_INDCUTOR [mm] "Inductor, CM, 4 line"
  rect 1.6x1.6 smd: 1(-3.81,-4.15) 2(-1.27,-4.15) 3(1.27,-4.15) 4(3.81,-4.15) 5(3.81,4.15) 6(1.27,4.15) 7(-1.27,4.15) 8(-3.81,4.15)
  silkscreen extent -5.5,-4.32 5.5,3.05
